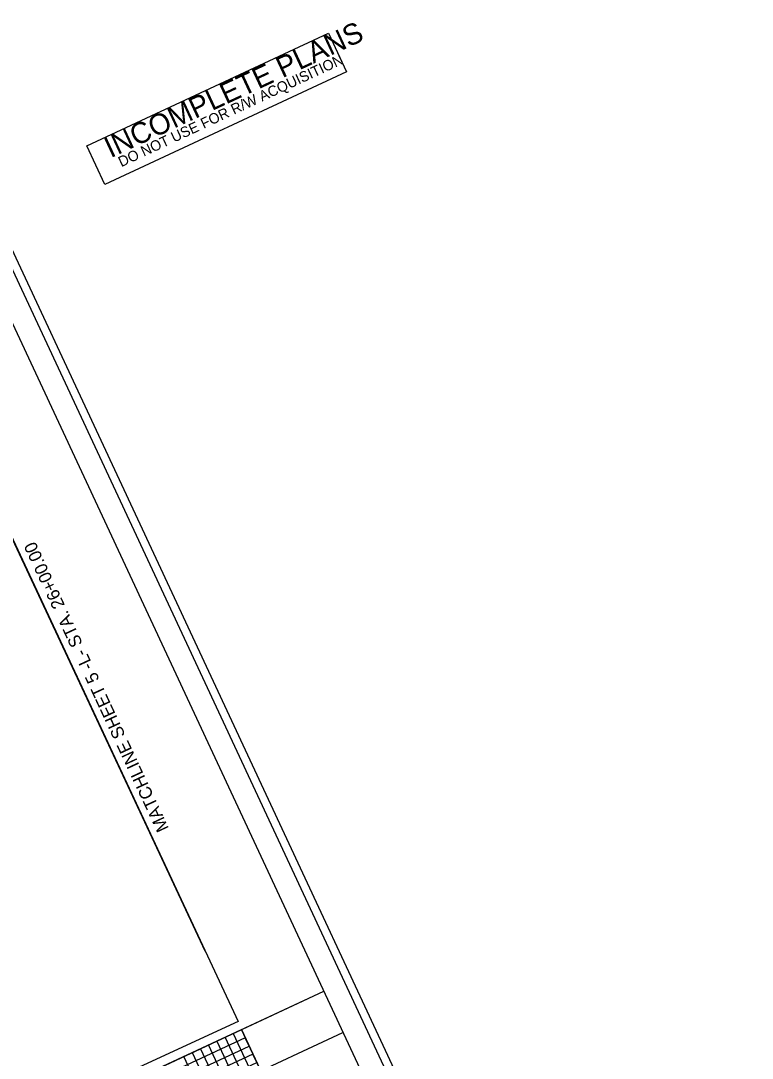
# Model space of a CAD drawing. Extents: x 2320593 to 2322597, y 921119 to 922832.
# Drawn here: x 2322194 to 2322597, y 922260 to 922832 of the extents above; entities that cross this region are included whole.
import ezdxf

# ---------------------------------------------------------------- set-up
doc = ezdxf.new("R2010")
doc.units = 0
for name, color, linetype in [('Matchline', 7, 'Continuous'), ('Matchline Text', 7, 'Continuous'), ('Sheet Cutting Line CELL', 7, 'Continuous'), ('Sheet DOT Grid CELL', 7, 'Continuous'), ('Sheet Layout Plan Border', 7, 'Continuous'), ('Sheet Layout Profile Border Port 2', 7, 'Continuous'), ('Sheet Plan And Profile CELL', 7, 'Continuous'), ('Sheet Plot Border Inside CELL', 7, 'Continuous'), ('Sheet Plot Border Outside CELL', 7, 'Continuous'), ('Sheet Profile Grid Major CELL', 7, 'Continuous'), ('Sheet Profile Grid Middle CELL', 7, 'Continuous'), ('Sheet Profile Grid Minor CELL', 7, 'Continuous'), ('Sheet Sticker Incomplete CELL', 7, 'Continuous')]:
    doc.layers.add(name, color=color, linetype=linetype)

# ---------------------------------------------------------------- blocks, each defined once
blk = doc.blocks.new('STICKER INCOMPLETE PLANS')
at = {"layer": 'Sheet Sticker Incomplete CELL'}
blk.add_lwpolyline([(0, -0.47), (0, 0), (2.94, 0), (2.94, -0.47)], close=True, dxfattribs=at)
for s, height, p in [('INCOMPLETE PLANS', 0.2304, (0.179, -0.236)), ('DO NOT USE FOR R/W ACQUISITION', 0.1152, (0.244, -0.375))]:
    blk.add_text(s, height=height, dxfattribs=at).set_placement(p)

msp = doc.modelspace()

# ---------------------------------------------------------------- linework, layer by layer
at = {"layer": 'Matchline'}
msp.add_line((2322150.95, 922627), (2322294.97, 922318.86), dxfattribs=at)
at = {"layer": 'Sheet DOT Grid CELL'}
for p, q in [((2321000.96, 921662.89), (2322360.52, 922296.61)), ((2322315.2, 922275.49), (2322515.88, 921844.96))]:
    msp.add_line(p, q, dxfattribs=at)
at = {"layer": 'Sheet Layout Plan Border'}
msp.add_lwpolyline([(2322313.35, 922279.99), (2321040.83, 921692.7), (2320815.91, 922178.3), (2322085.86, 922766.57)], close=True, dxfattribs=at)
at = {"layer": 'Sheet Layout Profile Border Port 2'}
msp.add_lwpolyline([(2321046.28, 921684.02), (2322315.2, 922275.49), (2322515.88, 921844.96), (2321246.96, 921253.49)], close=True, dxfattribs=at)
at = {"layer": 'Sheet Plan And Profile CELL'}
msp.add_lwpolyline([(2322128.15, 922795.12), (2320768.59, 922161.4), (2321212.2, 921209.71), (2322571.76, 921843.43)], close=True, dxfattribs=at)
at = {"layer": 'Sheet Plot Border Inside CELL'}
msp.add_lwpolyline([(2321074.13, 921142.59), (2322584.14, 921846.44), (2322138.43, 922802.66), (2320628.41, 922098.81)], close=True, dxfattribs=at)
at = {"layer": 'Sheet Plot Border Outside CELL'}
msp.add_lwpolyline([(2321070.79, 921118.97), (2322596.67, 921830.22), (2322134.06, 922822.69), (2320608.18, 922111.45)], close=True, dxfattribs=at)
at = {"layer": 'Sheet Profile Grid Major CELL'}
for points in [[(2321000.96, 921662.89), (2322360.52, 922296.61)], [(2322515.88, 921844.96), (2322315.2, 922275.49)]]:
    msp.add_lwpolyline(points, dxfattribs=at)
at = {"layer": 'Sheet Profile Grid Middle CELL'}
msp.add_line((2321011.52, 921640.23), (2322371.08, 922273.95), dxfattribs=at)
msp.add_lwpolyline([(2322447.9, 921813.28), (2322247.22, 922243.8), (2322292.54, 922264.93), (2322493.22, 921834.4)], dxfattribs=at)
at = {"layer": 'Sheet Profile Grid Minor CELL'}
for points in [[(2322506.81, 921840.74), (2322306.13, 922271.26), (2322310.67, 922273.38), (2322511.35, 921842.85)], [(2321050.5, 921674.95), (2322319.42, 922266.42), (2322317.31, 922270.96), (2321048.39, 921679.48)], [(2322497.75, 921836.51), (2322297.07, 922267.04), (2322301.6, 922269.15), (2322502.28, 921838.62)], [(2321054.73, 921665.89), (2322323.65, 922257.36), (2322321.54, 922261.89), (2321052.62, 921670.42)], [(2322484.15, 921830.17), (2322283.48, 922260.7), (2322288.01, 922262.81), (2322488.69, 921832.29)]]:
    msp.add_lwpolyline(points, dxfattribs=at)

# ---------------------------------------------------------------- block references
at = {"layer": 'Sheet Cutting Line CELL', "xscale": 49.99999999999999, "yscale": 50, "rotation": 24.991298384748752}
msp.add_blockref('STICKER INCOMPLETE PLANS', (2322229.97, 922762.82), dxfattribs=at)

# ---------------------------------------------------------------- texts
at = {"layer": 'Matchline Text'}
msp.add_text('MATCHLINE SHEET 5 -L- STA. 26+00.00', height=7, rotation=114.9913, dxfattribs=at).set_placement((2322275.35, 922386.46))

doc.saveas('drawing.dxf')
